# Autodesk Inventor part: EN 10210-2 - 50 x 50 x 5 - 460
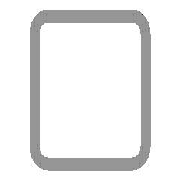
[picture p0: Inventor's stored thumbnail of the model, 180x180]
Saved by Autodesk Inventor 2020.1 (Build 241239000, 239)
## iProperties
Created: 2019-01
Part Number: EN 10210-2 - 50 x 50 x 5 - 460
Material: Stahl, weich
Description: Rohrleitung
Document SubType Name: Modeling
Standard: DIN
Designer: lutzd
Standard Revision: 2006-07
Standards Organization: DIN
Language: de-DE
Size Designation: 50 x 50 x 5
Categories: <MemberInstance><Categories><Category DisplayName="Profile" InternalName="089c4875-fa83-4c05-b084-43b9cc11f5ed" Mnemonic="GRDR"><CategoryParameter DisplayName="
Stock Number: 50 x 50 x 5
Mass: 3150.31 g
Surface Area: 1575.45 cm^2
Volume: 401.313 cm^3
Density: 7.85 g/cm^3
Appearance: Halbpoliert
IsCustomPart: 1
G_L: 460,000 mm
G_W: 50,000 mm
G_H: 50,000 mm
DocNumber: ADSK-014139
Folder: .
Dimensions: 50x50x460 mm
Mass: 3,15 kg
+454F8F75-554F-41F1-8FA6-F4C8FCEC9931+SCHNITTDETAIL1: Schnittwinkel 90,00 grd
_CCFamilyMember: 16
_CCFamilyDisplayName: DIN EN 10210-2 (USAS B17.1 quadratisch) - Rohrleitung — In Klammern angegebene Größen wurden aufgehoben
_FrameMemberDoc: Frame Member File
_Version: 15.0.0
_GetPNFromCC: 1
Title: Profil-Bauteil
Author: lutzd
Revision Number: -
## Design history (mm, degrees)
node "Startebene"
node "Endebene"
sketch "Skizze"
  geometry: L1 (-25, -17.5)-(-25, 17.5); L2 (-17.5, 25)-(17.5, 25); L3 (25, 17.5)-(25, -17.5); L4 (17.5, -25)-(-17.5, -25); L5 (-15, 20)-(15, 20); L6 (20, 15)-(20, -15); L7 (15, -20)-(-15, -20); L8 (-20, -15)-(-20, 15); L9 (0, 37.175)-(0, -37.175) reference; L10 (-37.175, 0)-(37.175, 0) reference; A1 r 7.5 centre (-17.5, -17.5) between (-25, -17.5) and (-17.5, -25); A2 r 7.5 centre (-17.5, 17.5) between (-17.5, 25) and (-25, 17.5); A3 r 7.5 centre (17.5, 17.5) between (25, 17.5) and (17.5, 25); A4 r 7.5 centre (17.5, -17.5) between (17.5, -25) and (25, -17.5); A5 r 5 centre (-15, -15) between (-20, -15) and (-15, -20); A6 r 5 centre (-15, 15) between (-15, 20) and (-20, 15); A7 r 5 centre (15, 15) between (20, 15) and (15, 20); A8 r 5 centre (15, -15) between (15, -20) and (20, -15)
  constraints: 16 end point, 16 point on circle, 16 tangent, 8 centre point, 6 equal radius, 4 parallel, 2 perpendicular, 2 other
  dimensions: "d7" = 7.5 radius of A1 (= G_IR); "d10" = 50 distance between parallel lines of L2 L4 (= G_H); "d11" = 50 distance between parallel lines of L1 L3 (= G_W); "d12" = 5 distance between parallel lines of L3 L6 (= G_T); "d15" = 25 distance between parallel lines of L2 L10 (= 0.5 x d10); "d16" = 25 distance between parallel lines of L9 L3 (= 0.5 x d11); "d19" = 5 radius of A5 (= G_T); "d20" = 5 distance between parallel lines of L4 L7 (= G_T)
extrude "Körper" new body sketch "Skizze" stored distance "d3" = 460 (= G_L); taper "d4" = 0 deg
node "Driven Length"
  sketch "Sketch3"
    geometry: L1 (0, 0)-(10, 0) reference
    constraints: 2 end point, 1 horizontal
  workplane "Work Plane3"
  sketch "Sketch4"
    geometry: L1 (-2, 25)-(12, 25) reference; L2 (-2, 485)-(12, 485) reference
    dimensions: "d18" = 460 distance between parallel lines of L1 L2 (derived)
workplane "Arbeitsebene4"
feature "Trennen1"
sketch "Skizze5"
  geometry: L1 (0, -35)-(0, 0) reference; L2 (0, -17.5)-(321, -17.5); 3 further points
  constraints: 2 end point, 1 coincident, 1 horizontal, 1 midpoint, 1 point on line
  dimensions: "d21" = 41 distance of point (280, -17.5) L2.end; "d22" = 280 distance from line of L1 point (280, -17.5)
hole "Bohrung1" sketch "Skizze5" at (321, -17.5), (280, -17.5) diameter "d23" = 6.647; stored, may be unused: countersink angle "d27" = 90 deg, drill point angle "d29" = 118 deg; dims "d24" = 16, "d25" = 4, "d26" = 2, "d28" = 22.2
body "Solid1"
other parameters: "G_W" = 50 [user parameter; used in 1 equation term], "G_H" = 50 [user parameter; used in 1 equation term], "G_T" = 5 [user parameter; used in 3 equation terms], "G_IR" = 7.5 [user parameter; used in 1 equation term], "G_L" = 460 (= d18) [user parameter; used in 1 equation term], "G_OFFSET_START" = -25 [user parameter; used in 1 equation term], "G_OFFSET_END" = 0 [user parameter; used in 1 equation term], "d13" = 25 (= -G_OFFSET_START), "d14" = 485 (= G_OFFSET_END + B_L), "B_L" = 485 [user parameter; used in 1 equation term], "d17" = 90 deg
